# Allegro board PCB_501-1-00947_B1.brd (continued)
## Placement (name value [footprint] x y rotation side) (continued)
R665  10K  [R0402]  25.37 35.81 270 top
R666  2.49K  [R0402]  25.87 37.46 0 top
R667  2.49K  [R0402]  26.51 35.81 90 top
R668  2.49K  [R0402]  28.03 30.73 90 top
R669  11K  [R0402]  39.08 29.08 270 bottom
R674  10K  [R0402]  124.3 47.75 270 top
R678  0E  [R0402]  88.1 42.29 90 top
R679  2.2K  [R0402]  89.25 42.29 270 top
R680  0E  [R0402]  29.56 33.53 180 top
R682  10K  [R0402]  104.74 12.32 180 top
R683  10K  [R0402]  123.16 47.75 90 top
R684  0E  [R0402]  90.9 42.8 180 top
R685  100K  [R0402]  18.13 80.9 270 bottom
R686  100K  [R0402]  22.83 94.36 180 top
R687  100K  [R0402]  19.52 80.9 270 bottom
R688  2.2K  [R0402]  26.89 33.53 180 top
R689  100K  [R0402]  8.6 66.55 0 top
R690  0E  [R0402]  22.83 93.34 0 top
R691  10K  [R0402]  68.04 60.58 0 bottom
R692  100K  [R0402]  118.97 65.91 0 top
R694  523K  [0402]  122.9 71.88 0 top
R695  16.9K  [0402]  121.38 71.88 0 top
R696  120K  [0402]  121.25 73.28 0 top
R697  10K  [R0402]  4.16 9.4 90 top
R698  10K  [R0402]  4.16 12.06 90 top
R699  10K  [R0402]  4.16 14.48 90 top
R700  10K  [R0402]  4.28 17.02 90 top
R701  10K  [R0402]  4.28 19.56 90 top
R702  10K  [R0402]  4.28 22.1 90 top
R703  10K  [R0402]  4.28 24.64 90 top
R704  10K  [R0402]  4.28 27.18 90 top
R705  10K  [R0402]  125.44 9.52 180 top
R706  33E  [R0402]  122.27 13.84 180 top
R707  10K  [R0402]  102.33 17.02 0 bottom
R708  10K  [R0402]  102.33 15.88 0 bottom
R709  10K  [R0402]  102.33 14.73 0 bottom
R710  10K  [R0402]  102.33 13.59 0 bottom
R711  10K  [R0402]  102.33 19.43 0 bottom
R715  100K  [R0402]  82.9 109.22 180 top
R716  10K  [0402]  87.72 115.06 90 top
R717  10K  [0402]  87.72 113.41 90 top
R718  10mE  [0603]  27.53 80.64 0 top
R721  10mE  [0603]  19.02 75.06 0 top
R722  10mE  [0603]  12.41 75.56 270 top
R723  0E  [R0402]  18.38 62.74 270 top
R724  0E  [R0402]  19.52 62.74 270 top
R725  0E  [R0402]  18.25 62.36 270 bottom
R726  0E  [R0402]  19.4 62.36 270 bottom
R727  10K  [R0402]  22.57 66.17 0 top
R728  10mE  [0603]  16.22 96.52 180 top
R729  10mE  [0603]  26.51 84.84 0 top
R730  10mE  [0603]  5.05 84.96 180 top
R731  10K  [R0402]  15.08 66.29 90 bottom
R732  10K  [R0402]  21.05 63.25 0 bottom
R733  0E  [R0402]  21.68 42.42 90 bottom
R734  100K  [R0402]  24.73 42.16 90 bottom
R735  100K  [R0402]  19.52 80.9 90 top
R736  0E  [R0402]  89.76 96.52 180 top
R737  0E  [R0402]  98.01 105.66 270 top
R738  1K  [R0402]  6.57 88.77 0 top
R739  470E  [R0402]  45.56 95.63 135 top
R740  470E  [R0402]  44.42 94.36 135 top
R741  4.7K  [R0402]  41.59 37.16 0 bottom
R742  100K  [R0402]  103.22 61.72 0 bottom
R749  10K  [R0402]  11.52 91.82 270 top
R750  10K  [R0402]  25.24 93.85 90 top
R751  100K  [R0402]  16.35 81.28 180 bottom
R752  0E  [R0402]  12.54 91.82 90 top
R753  100K  [R0402]  69.69 87.25 45 bottom
R754  0E  [R0402]  120.13 26.14 90 top
R755  0E  [R0402]  117.82 26.04 90 top
R756  0E  [R0402]  120.62 25.65 0 top
R757  0E  [R0402]  118.31 25.55 0 top
R758  470E  [R0402]  10.89 53.47 180 top
R762  0E  [R0402]  21.4 95.96 90 top
R763  100K  [R0402]  15.05 78.82 270 bottom
R764  100K  [R0402]  10.35 80.21 270 bottom
SW1  OS102011MS2QN1  [SW3_2_8P6X4P3_TH_ST]  43.53 126.11 0 top
SW2  219-8MST  [SW16_2P54_21P79X6P7_A1]  11.02 18.8 270 top
SW3  219-2MST  [SW4_2P54_6P95X6P55]  11.02 34.42 0 top
SW4  TL6700AF160QG  [SW4_4_6P9X6P2]  4.54 73.28 270 top
SW5  TL6700AF160QG  [SW4_4_6P9X6P2]  102.2 54.36 0 top
SW6  TL6700AF160QG  [SW4_4_6P9X6P2]  102.46 65.79 0 top
SW7  TL6700AF160QG  [SW4_4_6P9X6P2]  121.63 54.36 0 top
SW8  TL6700AF160QG  [SW4_4_6P9X6P2]  88.87 73.03 90 top
SW9  SDA01H0SB  [SW2_8P25_7P49X4P52]  35.53 87.88 0 top
TP1  SMD  [TP30]  20.29 99.06 90 top
TP6  SMD  [TP30]  75.23 82.2 270 top
TP7  SMD  [TP30]  76.34 83.67 225 top
TP8  SMD  [TP30]  78.16 83.41 225 top
TP9  SMD  [TP30]  79.73 82.08 225 top
TP10  SMD  [TP30]  54.45 92.58 180 bottom
TP11  SMD  [TP30]  57.82 91.08 135 bottom
TP14  SMD  [TP30]  66.38 100.43 90 bottom
TP15  SMD  [TP15]  65.93 97.05 0 top
TP16  SMD  [TP15]  71.83 102.1 0 top
TP17  SMD  [TP15]  51.35 101.44 0 top
TP18  SMD  [TP15]  54.34 98.45 0 top
TP19  SMD  [TP30]  67.82 100.46 90 bottom
TP20  SMD  [TP30]  52.42 99.06 270 top
TP21  SMD  [TP15]  69.12 110.34 90 bottom
TP22  SMD  [TP15]  51.68 111.43 180 bottom
TP23  SMD  [TP15]  70.28 111.41 90 bottom
TP24  SMD  [TP15]  52.7 112.32 90 bottom
TP29  SMD  [TP30]  103.85 38.73 270 bottom
TP30  SMD  [TP40_SMD]  24.73 45.72 0 top
TP31  SMD  [TP40_SMD]  5.43 30.23 0 top
TP32  SMD  [TP40_SMD]  6.82 99.95 0 top
TP33  SMD  [TP40_SMD]  63.85 35.94 0 top
TP34  SMD  [TP40_SMD]  68.55 23.62 0 top
TP35  SMD  [TP40_SMD]  124.68 61.34 0 top
TP36  SMD  [TP40_SMD]  78.45 114.17 0 top
TP37  SMD  [TP40_SMD]  76.67 111.51 0 top
TP40  SMD  [TP15]  67.96 101.24 0 top
TP41  SMD  [TP15]  64.29 99.03 0 top
TP42  SMD  [TP15]  68.33 102.18 0 top
TP43  SMD  [TP15]  64 97.91 0 top
TP44  SMD  [TP15]  57.56 97.13 0 top
TP45  SMD  [TP15]  57.28 98.09 0 top
TP46  SMD  [TP15]  53.86 100.86 0 top
TP47  SMD  [TP15]  53.92 101.47 0 top
TP48  SMD  [TP30]  54.53 75.54 90 bottom
TP50  SMD  [TP40_SMD]  113.5 25.53 270 top
TP51  SMD  [TP40_SMD]  115.92 26.04 270 top
TP52  SMD  [TP40_SMD]  123.16 26.04 270 top
TP53  SMD  [TP40_SMD]  122.01 24.26 270 top
TP54  SMD  [TP40_SMD]  125.95 17.4 270 top
TP55  SMD  [TP40_SMD]  125.95 19.18 270 top
TP56  SMD  [TP40_SMD]  103.85 4.06 270 top
TP57  SMD  [TP40_SMD]  105.38 4.06 270 top
TP62  SMD  [TP40_SMD]  49.12 34.29 0 top
TP68  SMD  [TP30]  61.96 108.31 0 top
TP69  SMD  [TP30]  67.95 97.08 0 top
TP70  SMD  [TP30]  76.49 107.96 0 top
TP71  SMD  [TP30]  70.52 118.42 0 top
TP72  SMD  [TP30]  60.03 121.04 0 top
TP73  SMD  [TP30]  46.34 108.31 0 top
TP74  SMD  [TP30]  49.13 118.12 0 top
TP75  SMD  [TP30]  47.78 100.56 0 top
TP76  SMD  [TP30]  82.39 107.7 270 top
TP77  SMD  [TP40_SMD]  11.44 71.16 0 top
TP78  SMD  [TP40_SMD]  25.11 70.1 0 top
TP79  SMD  [TP40_SMD]  31.34 80.52 0 top
TP80  SMD  [TP40_SMD]  7.59 98.04 0 top
TP81  SMD  [TP40_SMD]  28.67 85.72 0 top
TP82  SMD  [TP40_SMD]  2 86.36 0 top
TP83  SMD  [TP40_SMD]  106.41 47.6 270 top
TP84  SMD  [TP40_SMD]  124.93 78.74 0 top
TP85  SMD  [TP40_SMD]  23.21 49.91 0 top
TP86  SMD  [TP40_SMD]  57.04 38.83 0 top
U5  TPS65218D0RSL  [VQFN48_0P4_6X6_EP_A1]  16.48 86.87 180 top
U7  MCIMX7D5EVM10SD  [BGA541X]  60.99 86.3 135 top
U8  MT41K256M16TW-107:P  [BGA96_0P8_8P15X14P15]  70.11 109.22 180 top
U9  MT41K256M16TW-107:P  [BGA96_0P8_8P15X14P15]  52.95 109.22 180 top
U10  MTFC8GAKAJCN-4M  [BGA153_0P5_11P5X13_C_A1]  71.61 59.9 315 top
U11  MT25QL512ABB1EW9  [DFN8_1P27_8X6_EP_A_A1]  44.23 99.59 90 bottom
U13  DP83867CRRGZ  [QFN48_0P5_7X7_EP_O_A1]  35.53 34.54 90 top
U17  SN74LVC2G126DCU  [DCU8P5R]  112.6 110.34 0 bottom
U18  FT2232D  [QFP48P5J]  104.73 112.88 270 bottom
U19  SN74LVC2G126DCU  [DCU8P5R]  102.85 104.55 90 bottom
U23  TSC2046IPW  [TSSOP16FA]  17.65 48.92 90 bottom
U24  WM8960CGEFL  [QFN32_1P5H]  96.54 39.04 180 top
U25  MCP2562-E/MF  [DFN8_0P65_3X3_EP_A]  74.64 23.5 180 top
U30  LM3526MX-L/NOPB  [SOIC8_1P27_4X5]  57.75 17.27 270 bottom
U31  OPT3001DNP  [SON6_0P65_2X2_EP_A_A1]  121 47.24 180 top
U33  SN74LVC1G07DBV  [SOT23-5L_0P95_3P05X1P75]  11.14 58.55 90 top
U37  TPS3808G25  [SOT23-6L_0P95_3P05X1P75]  90.77 93.09 270 top
U41  24AA512  [SO8_1P27_4X5]  91.28 60.96 180 top
U42  PI6CG182Q2ZDQ  [QFN24_0P5_4X4_EP_R_A1]  79.46 97.5 225 top
U45  TXS0102DCU  [SSOP8CR]  29.02 56.83 0 top
U46  TPS62067DSG  [SON8_0P5_2X2_EP]  122.01 65.66 90 top
U47  TLV75528PDQN  [X2SON4_0P65_1X1_EP_A_A1]  28.16 48.13 0 top
U49  TLV75525PDQN  [X2SON4_0P65_1X1_EP_A_A1]  63.09 37.97 0 top
U50  INA3221AIRGV  [QFN16_0P65_4X4_EP_I_A1]  18.89 66.55 0 top
U51  TPS51200DRC  [SON10_0P5_3P1X3P1]  81.88 112.52 180 top
U52  INA3221AIRGV  [QFN16_0P65_4X4_EP_I_A1]  18.89 66.55 180 bottom
U53  PUSB3F96  [DFN2510A-10L_0P5_2P5X1]  25.75 23.5 0 top
U54  PUSB3F96  [DFN2510A-10L_0P5_2P5X1]  31.59 23.5 0 top
U55  BD2204GUL  [VCSP50L1-6_0P5_1P5X1_A1]  103.34 63.5 270 bottom
X1  32.768KHz  [XTAL2_2P5_3P2X1P5]  81.12 86.36 225 top
X2  24MHz  [XTAL4_1P85_3P2X2P5]  76.93 77.72 45 top
X3  25MHz  [XTAL4_1P7_3P2X2P5]  44.67 32 270 top
X4  25MHz  [XTAL2_3P8_5X3P2]  85.18 102.23 135 top
X5  6MHz  [XTAL4_2P54_7X5_A_A1]  92.68 113.41 90 bottom
Y4  24MHz  [OSC4_1P9_3P2X2P5_C_A1]  4.41 47.5 270 bottom
Y5  32.768KHz  [OSC4_3P2X2P5_SMD]  125.19 12.7 90 top

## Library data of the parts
BH1 = BATT_HOLDER_2P
C1 C199 C202-C204 C274 C275 C299 C438 = CAP_POL
C2 C3 C40-C42 C44-C53 C63-C131 C140-C190 C194-C197 C200 C201 C207 C208 C216-C224 C226-C228 C239-C245 C249-C252 C260-C273 C276 C279-C298 C300-C311 C318 C354 C357 C361 C362 C366-C370 C382 C391-C395 C401-C410 C420-C423 C439 C444-C448 C456 C460 C461 C500 C501 C503-C513 C518-C520 C523-C525 C527-C531 C533-C540 C542-C544 C546 C550-C553 C556-C561 C566-C579 = CAP_NP
D1 D2 D6-D11 D14 D33 D35 = DIODE_LED
D4 D16 D20-D22 D26 D34 = DIODE_SCH
D5 = DIODE_LED_A
D17 = DIODE_ZEN
D23 D24 D27-D30 = DIODE_TVS_BIDIR_C_A1
DA1 = DIODE_NETX2_LED-GR_4P
F1 = FUSE
FB2-FB4 FB10-FB14 FB16-FB22 FB31 FB32 FB35-FB42 = FER_BEAD
FD1-FD6 = MECH_FID_G
FD7-FD14 = MECH_FID_L
FL1 FL2 = FIL_COM-MODE_4P_C_POL
FL3 = FIL_COM-MODE_4P_C_POL: signal model: FIL_COM-MODE_4P_C_POL_CM_CHK4_0
H1 H2 = HDR_2X5_10P
H3 = HDR_1X4_4P
H4 = HDR_1X3_3P
H5 = HDR_1X6_6P
J1 = CONN_PWRJACK_4P_A_A1
J2 = CONN_B2C_1X2_2P
J3 J4 J10 = CONN_COAX_3P
J7 = CONN_SIMCARD_8P
J8 = CONN_MINI-PCIEXPRESS-52_54P_A
J11 = CONN_USB-5X1_11P
J14 = CONN_FPC-50_52P
J15 = CONN_AUDJACK_4P
J19 = CONN_DB9X1_11P
J20 = CONN_B2B_2X15_34P_A
J25 = CONN_USB-5X1_7P
J26 = CONN_USBA-4X1_8P
J27 = CONN_RJ45-14X1_16P_A
J28 = CONN_SD-CARD-11_14P_A1
L3-L6 = IND_CORE_A
L7 = IND_CORE_B
L8 = IND_POL
M1 = MODRF_WL1831_100P
MECH1-MECH4 = MECH_STANDOFF_A1
MH1-MH4 = MECH_MH_PL
MK1 = MICROPHONE
P4-P8 P10-P14 P17-P27 = PROT_ZENX2_NET_2P_A
Q2 Q32 Q34 = TRANS_PMOSX1_8P
Q5 Q7 Q25 Q37 Q39 = TRANS_NMOS-ENX1_3P
Q6 Q24 = TRANS_PMOS-ENX1_3P_E
Q8 Q40 Q41 = TRANS_NPN
Q17 = TRANS_PNP
Q35 = TRANS_PNPX2_6P_A1
Q38 = TRANS_PMOS-ENX1_3P_C
R1 R4 R6 R8 R12 R30-R38 R45-R47 R49 R61-R71 R75 R76 R80-R86 R90-R94 R99 R102-R105 R107-R110 R116-R118 R125-R127 R129-R131 R145-R147 R155 R157-R172 R174 R176-R182 R203 R204 R206 R209-R213 R224 R231-R238 R242 R245-R247 R249-R255 R257 R269 R284 R285 R293-R297 R301-R303 R307-R310 R325 R347-R350 R356-R358 R366 R367 R380 R381 R387 R483 R485-R487 R491 R504 R506 R508 R509 R515 R516 R520 R521 R537-R539 R558 R559 R565-R571 R590-R593 R595-R598 R604-R608 R613-R618 R622 R623 R630 R632-R641 R644 R645 R656 R658 R660 R663-R669 R674 R678-R680 R682-R692 R694-R711 R715-R718 R721-R742 R749-R758 R762-R764 = RES
R39-R44 R100 R101 R106 = RES: signal model: sd1
R95-R97 R124 R278-R283 R300 R306 R436-R447 = RES: signal model: sd3
R286-R291 = RES: signal model: sd2
R448 R449 = RES: signal model: nand
R525-R528 R530 R532 = RES: signal model: RGMII1_TX
SW1 = SWITCH_SPDT_5P
SW2 = SWITCH_DIPX8_16P_B
SW3 = SWITCH_DIPX2_4P_B
SW4-SW8 = SWITCH_PUSH_4P
SW9 = SWITCH_DIPX1_2P_B
TP1 TP6-TP11 TP14-TP24 TP29-TP37 TP40-TP48 TP50-TP57 TP62 TP68-TP86 = TEST_POINT_SMD
U5 = IC_TPS65218D0_QFN-48P_EP_A1
U7 = IC_IMX7D_BGA-541P_CUST_A1
U8 U9 = IC_DDR3-SDRAM_BGA-96P_CUST_A1
U10 = IC_NAND_FLASHx8_BGA-153P_J_A1
U11 = IC_NORFLASH-SPI_8P_EP_G_A1
U13 = IC_DP83867_VQFN-48P_EP_A_A1
U17 U19 = IC_GATE_BUFX2_8P_B_A1
U18 = IC_FT2232D_LQFP-48P_A1
U23 = IC_TSC2046_TSSOP-16P_A1
U24 = IC_AUDIO-CODEC_32P_EP_A_A1
U25 = IC_CAN-XCVR_8P_EP_A2
U30 = IC_LM3526-L_SOIC-8P
U31 = IC_LIGHT-SENSOR_6P_EP_B_A1
U33 = IC_GATE_BUFX1_5P
U37 = IC_VOLT-MONITOR_6P
U41 = IC_EEPROM-I2C_8P_C
U42 = IC_CLOCK-GENERATOR_24P_EP_C_A1
U45 = IC_TXS0102_8P_A
U46 = IC_TPS62067_WSON-8P_EP
U47 U49 = IC_LDO-FIXED_4P_EP_A_A2
U50 U52 = IC_INA3221_VQFN-16P_EP_A1
U51 = IC_TPS51200_SON-10P_EP
U53 U54 = IC_PUSB3F96_DFN-10P
U55 = IC_BD2204_CSP-6P_A1
X1 X4 = CRYSTAL
X2 X3 X5 = CRYSTAL_4P
Y4 = OSC_4P_R_A1
Y5 = OSC_4P_A

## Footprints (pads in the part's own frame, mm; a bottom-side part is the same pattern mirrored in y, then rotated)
0402
  rect 0.533x0.533 smd: 1(-0.4,0) 2(0.4,0)
0603
  rect 0.965x1.016 smd: 1(-0.8,0) 2(0.8,0)
0805_B_A1
  rect 0.711x1.321 smd: 1(-0.95,0) 2(0.95,0)
BGA96_0P8_8P15X14P15
  round 0.356 smd: A1(-3.2,6) A2(-2.4,6) A3(-1.6,6) A7(1.6,6) A8(2.4,6) A9(3.2,6) B1(-3.2,5.2) B2(-2.4,5.2) B3(-1.6,5.2) B7(1.6,5.2) B8(2.4,5.2) B9(3.2,5.2) C1(-3.2,4.4) C2(-2.4,4.4) C3(-1.6,4.4) C7(1.6,4.4) C8(2.4,4.4) C9(3.2,4.4) D1(-3.2,3.6) D2(-2.4,3.6) D3(-1.6,3.6) D7(1.6,3.6) D8(2.4,3.6) D9(3.2,3.6) E1(-3.2,2.8) E2(-2.4,2.8) E3(-1.6,2.8) E7(1.6,2.8) E8(2.4,2.8) E9(3.2,2.8) F1(-3.2,2) F2(-2.4,2) F3(-1.6,2) F7(1.6,2) F8(2.4,2) F9(3.2,2) G1(-3.2,1.2) G2(-2.4,1.2) G3(-1.6,1.2) G7(1.6,1.2) G8(2.4,1.2) G9(3.2,1.2) H1(-3.2,0.4) H2(-2.4,0.4) H3(-1.6,0.4) H7(1.6,0.4) H8(2.4,0.4) H9(3.2,0.4) J1(-3.2,-0.4) J2(-2.4,-0.4) J3(-1.6,-0.4) J7(1.6,-0.4) J8(2.4,-0.4) J9(3.2,-0.4) K1(-3.2,-1.2) K2(-2.4,-1.2) K3(-1.6,-1.2) K7(1.6,-1.2) K8(2.4,-1.2) K9(3.2,-1.2) L1(-3.2,-2) L2(-2.4,-2) L3(-1.6,-2) L7(1.6,-2) L8(2.4,-2) L9(3.2,-2) M1(-3.2,-2.8) M2(-2.4,-2.8) M3(-1.6,-2.8) M7(1.6,-2.8) M8(2.4,-2.8) M9(3.2,-2.8) N1(-3.2,-3.6) N2(-2.4,-3.6) N3(-1.6,-3.6) N7(1.6,-3.6) N8(2.4,-3.6) N9(3.2,-3.6) P1(-3.2,-4.4) P2(-2.4,-4.4) P3(-1.6,-4.4) P7(1.6,-4.4) P8(2.4,-4.4) P9(3.2,-4.4) R1(-3.2,-5.2) R2(-2.4,-5.2) R3(-1.6,-5.2) R7(1.6,-5.2) R8(2.4,-5.2) R9(3.2,-5.2) T1(-3.2,-6) T2(-2.4,-6) T3(-1.6,-6) T7(1.6,-6) T8(2.4,-6) T9(3.2,-6)
BGA153_0P5_11P5X13_C_A1
  round 0.254 smd: A1(-3.25,3.25) A2(-2.75,3.25) A3(-2.25,3.25) A4(-1.75,3.25) A5(-1.25,3.25) A6(-0.75,3.25) A7(-0.25,3.25) A8(0.25,3.25) A9(0.75,3.25) A10(1.25,3.25) A11(1.75,3.25) A12(2.25,3.25) A13(2.75,3.25) A14(3.25,3.25) B1(-3.25,2.75) B2(-2.75,2.75) B3(-2.25,2.75) B4(-1.75,2.75) B5(-1.25,2.75) B6(-0.75,2.75) B7(-0.25,2.75) B8(0.25,2.75) B9(0.75,2.75) B10(1.25,2.75) B11(1.75,2.75) B12(2.25,2.75) B13(2.75,2.75) B14(3.25,2.75) C1(-3.25,2.25) C2(-2.75,2.25) C3(-2.25,2.25) C4(-1.75,2.25) C5(-1.25,2.25) C6(-0.75,2.25) C7(-0.25,2.25) C8(0.25,2.25) C9(0.75,2.25) C10(1.25,2.25) C11(1.75,2.25) C12(2.25,2.25) C13(2.75,2.25) C14(3.25,2.25) D1(-3.25,1.75) D2(-2.75,1.75) D3(-2.25,1.75) D4(-1.75,1.75) D12(2.25,1.75) D13(2.75,1.75) D14(3.25,1.75) E1(-3.25,1.25) E2(-2.75,1.25) E3(-2.25,1.25) E5(-1.25,1.25) E6(-0.75,1.25) E7(-0.25,1.25) E8(0.25,1.25) E9(0.75,1.25) E10(1.25,1.25) E12(2.25,1.25) E13(2.75,1.25) E14(3.25,1.25) F1(-3.25,0.75) F2(-2.75,0.75) F3(-2.25,0.75) F5(-1.25,0.75) F10(1.25,0.75) F12(2.25,0.75) F13(2.75,0.75) F14(3.25,0.75) G1(-3.25,0.25) G2(-2.75,0.25) G3(-2.25,0.25) G5(-1.25,0.25) G10(1.25,0.25) G12(2.25,0.25) G13(2.75,0.25) G14(3.25,0.25) H1(-3.25,-0.25) H2(-2.75,-0.25) H3(-2.25,-0.25) H5(-1.25,-0.25) H10(1.25,-0.25) H12(2.25,-0.25) H13(2.75,-0.25) H14(3.25,-0.25) J1(-3.25,-0.75) J2(-2.75,-0.75) J3(-2.25,-0.75) J5(-1.25,-0.75) J10(1.25,-0.75) J12(2.25,-0.75) J13(2.75,-0.75) J14(3.25,-0.75) K1(-3.25,-1.25) K2(-2.75,-1.25) K3(-2.25,-1.25) K5(-1.25,-1.25) K6(-0.75,-1.25) K7(-0.25,-1.25) K8(0.25,-1.25) K9(0.75,-1.25) K10(1.25,-1.25) K12(2.25,-1.25) K13(2.75,-1.25) K14(3.25,-1.25) L1(-3.25,-1.75) L2(-2.75,-1.75) L3(-2.25,-1.75) L12(2.25,-1.75) L13(2.75,-1.75) L14(3.25,-1.75) M1(-3.25,-2.25) M2(-2.75,-2.25) M3(-2.25,-2.25) M4(-1.75,-2.25) M5(-1.25,-2.25) M6(-0.75,-2.25) M7(-0.25,-2.25) M8(0.25,-2.25) M9(0.75,-2.25) M10(1.25,-2.25) M11(1.75,-2.25) M12(2.25,-2.25) M13(2.75,-2.25) M14(3.25,-2.25) N1(-3.25,-2.75) N2(-2.75,-2.75) N3(-2.25,-2.75) N4(-1.75,-2.75) N5(-1.25,-2.75) N6(-0.75,-2.75) N7(-0.25,-2.75) N8(0.25,-2.75) N9(0.75,-2.75) N10(1.25,-2.75) N11(1.75,-2.75) N12(2.25,-2.75) N13(2.75,-2.75) N14(3.25,-2.75) P1(-3.25,-3.25) P2(-2.75,-3.25) P3(-2.25,-3.25) P4(-1.75,-3.25) P5(-1.25,-3.25) P6(-0.75,-3.25) P7(-0.25,-3.25) P8(0.25,-3.25) P9(0.75,-3.25) P10(1.25,-3.25) P11(1.75,-3.25) P12(2.25,-3.25) P13(2.75,-3.25) P14(3.25,-3.25)
BGA541X
  round 0.381 smd: A1(-9,9) A2(-8.25,9) A3(-7.5,9) A4(-6.75,9) A5(-6,9) A6(-5.25,9) A7(-4.5,9) A8(-3.75,9) A9(-3,9) A10(-2.25,9) A11(-1.5,9) A12(-0.75,9) A13(0,9) A14(0.75,9) A15(1.5,9) A16(2.25,9) A17(3,9) A18(3.75,9) A19(4.5,9) A20(5.25,9) A21(6,9) A22(6.75,9) A23(7.5,9) A24(8.25,9) A25(9,9) AA1(-9,-6) AA2(-8.25,-6) AA3(-7.5,-6) AA4(-6.75,-6) AA5(-6,-6) AA6(-5.25,-6) AA7(-4.5,-6) AA8(-3.75,-6) AA9(-3,-6) AA10(-2.25,-6) AA11(-1.5,-6) AA12(-0.75,-6) AA13(0,-6) AA14(0.75,-6) AA15(1.5,-6) AA16(2.25,-6) AA17(3,-6) AA18(3.75,-6) AA19(4.5,-6) AA20(5.25,-6) AA21(6,-6) AA22(6.75,-6) AA23(7.5,-6) AA24(8.25,-6) AA25(9,-6) AB1(-9,-6.75) AB2(-8.25,-6.75) AB3(-7.5,-6.75) AB4(-6.75,-6.75) AB5(-6,-6.75) AB6(-5.25,-6.75) AB7(-4.5,-6.75) AB8(-3.75,-6.75) AB9(-3,-6.75) AB10(-2.25,-6.75) AB11(-1.5,-6.75) AB12(-0.75,-6.75) AB13(0,-6.75) AB14(0.75,-6.75) AB15(1.5,-6.75) AB16(2.25,-6.75) AB17(3,-6.75) AB18(3.75,-6.75) AB19(4.5,-6.75) AB20(5.25,-6.75) AB21(6,-6.75) AB22(6.75,-6.75) AB23(7.5,-6.75) AB24(8.25,-6.75) AB25(9,-6.75) AC1(-9,-7.5) AC2(-8.25,-7.5) AC3(-7.5,-7.5) AC4(-6.75,-7.5) AC5(-6,-7.5) AC6(-5.25,-7.5) AC7(-4.5,-7.5) AC8(-3.75,-7.5) AC9(-3,-7.5) AC10(-2.25,-7.5) AC11(-1.5,-7.5) AC12(-0.75,-7.5) AC13(0,-7.5) AC14(0.75,-7.5) AC15(1.5,-7.5) AC16(2.25,-7.5) AC17(3,-7.5) AC18(3.75,-7.5) AC19(4.5,-7.5) AC20(5.25,-7.5) AC21(6,-7.5) AC22(6.75,-7.5) AC23(7.5,-7.5) AC24(8.25,-7.5) AC25(9,-7.5) AD1(-9,-8.25) AD2(-8.25,-8.25) AD3(-7.5,-8.25) AD4(-6.75,-8.25) AD5(-6,-8.25) AD6(-5.25,-8.25) AD7(-4.5,-8.25) AD8(-3.75,-8.25) AD9(-3,-8.25) AD10(-2.25,-8.25) AD11(-1.5,-8.25) AD12(-0.75,-8.25) AD13(0,-8.25) AD14(0.75,-8.25) AD15(1.5,-8.25) AD16(2.25,-8.25) AD17(3,-8.25) AD18(3.75,-8.25) AD19(4.5,-8.25) AD20(5.25,-8.25) AD21(6,-8.25) AD22(6.75,-8.25) AD23(7.5,-8.25) AD24(8.25,-8.25) AD25(9,-8.25) AE1(-9,-9) AE2(-8.25,-9) AE3(-7.5,-9) AE4(-6.75,-9) AE5(-6,-9) AE6(-5.25,-9) AE7(-4.5,-9) AE8(-3.75,-9) AE9(-3,-9) AE10(-2.25,-9) AE11(-1.5,-9) AE12(-0.75,-9) AE13(0,-9) AE14(0.75,-9) AE15(1.5,-9) AE16(2.25,-9) AE17(3,-9) AE18(3.75,-9) AE19(4.5,-9) AE20(5.25,-9) AE21(6,-9) AE22(6.75,-9) AE23(7.5,-9) AE24(8.25,-9) AE25(9,-9) B1(-9,8.25) B2(-8.25,8.25) B3(-7.5,8.25) B4(-6.75,8.25) B5(-6,8.25) B6(-5.25,8.25) B7(-4.5,8.25) B8(-3.75,8.25) B9(-3,8.25) B10(-2.25,8.25) B11(-1.5,8.25) B12(-0.75,8.25) B13(0,8.25) B14(0.75,8.25) B15(1.5,8.25) B16(2.25,8.25) B17(3,8.25) B18(3.75,8.25) B19(4.5,8.25) B20(5.25,8.25) B21(6,8.25) B22(6.75,8.25) B23(7.5,8.25) B24(8.25,8.25) B25(9,8.25) C1(-9,7.5) C2(-8.25,7.5) C3(-7.5,7.5) C4(-6.75,7.5) C5(-6,7.5) C6(-5.25,7.5) C7(-4.5,7.5) C8(-3.75,7.5) C9(-3,7.5) C10(-2.25,7.5) C11(-1.5,7.5) C12(-0.75,7.5) C13(0,7.5) C14(0.75,7.5) C15(1.5,7.5) C16(2.25,7.5) C17(3,7.5) C18(3.75,7.5) C19(4.5,7.5) C20(5.25,7.5) C21(6,7.5) C22(6.75,7.5) C23(7.5,7.5) C24(8.25,7.5) C25(9,7.5) D1(-9,6.75) D2(-8.25,6.75) D3(-7.5,6.75) D4(-6.75,6.75) D5(-6,6.75) D6(-5.25,6.75) D7(-4.5,6.75) D8(-3.75,6.75) D9(-3,6.75) D10(-2.25,6.75) D11(-1.5,6.75) D12(-0.75,6.75) D13(0,6.75) D14(0.75,6.75) D15(1.5,6.75) D16(2.25,6.75) D17(3,6.75) D18(3.75,6.75) D19(4.5,6.75) D20(5.25,6.75) D21(6,6.75) D22(6.75,6.75) D23(7.5,6.75) D24(8.25,6.75) D25(9,6.75) E1(-9,6) E2(-8.25,6) E3(-7.5,6) E4(-6.75,6) E5(-6,6) E6(-5.25,6) E7(-4.5,6) E8(-3.75,6) E9(-3,6) E10(-2.25,6) E11(-1.5,6) E12(-0.75,6) E13(0,6) E14(0.75,6) E15(1.5,6) E16(2.25,6) E17(3,6) E18(3.75,6) E19(4.5,6) E20(5.25,6) E21(6,6) E22(6.75,6) E23(7.5,6) E24(8.25,6) E25(9,6) F1(-9,5.25) F2(-8.25,5.25) F3(-7.5,5.25) F4(-6.75,5.25) F5(-6,5.25) F6(-5.25,5.25) F7(-4.5,5.25) F8(-3.75,5.25) F9(-3,5.25) F10(-2.25,5.25) F11(-1.5,5.25) F12(-0.75,5.25) F13(0,5.25) F14(0.75,5.25) F15(1.5,5.25) F16(2.25,5.25) F17(3,5.25) F18(3.75,5.25) F19(4.5,5.25) F20(5.25,5.25) F21(6,5.25) F22(6.75,5.25) F23(7.5,5.25) F24(8.25,5.25) F25(9,5.25) G1(-9,4.5) G2(-8.25,4.5) G3(-7.5,4.5) G4(-6.75,4.5) G5(-6,4.5) G6(-5.25,4.5) G7(-4.5,4.5) G9(-3,4.5) G11(-1.5,4.5) G13(0,4.5) G15(1.5,4.5) G17(3,4.5) G19(4.5,4.5) G20(5.25,4.5) G21(6,4.5) G22(6.75,4.5) G23(7.5,4.5) G24(8.25,4.5) G25(9,4.5) H1(-9,3.75) H2(-8.25,3.75) H3(-7.5,3.75) H4(-6.75,3.75) H5(-6,3.75) H6(-5.25,3.75) H8(-3.75,3.75) H10(-2.25,3.75) H12(-0.75,3.75) H14(0.75,3.75) H16(2.25,3.75) H18(3.75,3.75) H20(5.25,3.75) H21(6,3.75) H22(6.75,3.75) H23(7.5,3.75) H24(8.25,3.75) H25(9,3.75) J1(-9,3) J2(-8.25,3) J3(-7.5,3) J4(-6.75,3) J5(-6,3) J6(-5.25,3) J7(-4.5,3) J9(-3,3) J11(-1.5,3) J13(0,3) J15(1.5,3) J17(3,3) J19(4.5,3) J20(5.25,3) J21(6,3) J22(6.75,3) J23(7.5,3) J24(8.25,3) J25(9,3) K1(-9,2.25) K2(-8.25,2.25) K3(-7.5,2.25) K4(-6.75,2.25) K5(-6,2.25) K6(-5.25,2.25) K8(-3.75,2.25) K10(-2.25,2.25) K12(-0.75,2.25) K14(0.75,2.25) K16(2.25,2.25) K18(3.75,2.25) K20(5.25,2.25) K21(6,2.25) K22(6.75,2.25) K23(7.5,2.25) K24(8.25,2.25) K25(9,2.25) L1(-9,1.5) L2(-8.25,1.5) L3(-7.5,1.5) L4(-6.75,1.5) L5(-6,1.5) L6(-5.25,1.5) L7(-4.5,1.5) L9(-3,1.5) L11(-1.5,1.5) L13(0,1.5) L15(1.5,1.5) L17(3,1.5) L19(4.5,1.5) L20(5.25,1.5) L21(6,1.5) L22(6.75,1.5) L23(7.5,1.5) L24(8.25,1.5) L25(9,1.5) M1(-9,0.75) M2(-8.25,0.75) M3(-7.5,0.75) M4(-6.75,0.75) M5(-6,0.75) M6(-5.25,0.75) M8(-3.75,0.75) M10(-2.25,0.75) M12(-0.75,0.75) M14(0.75,0.75) M16(2.25,0.75) M18(3.75,0.75) M20(5.25,0.75) M21(6,0.75) M22(6.75,0.75) M23(7.5,0.75) M24(8.25,0.75) M25(9,0.75) N1(-9,0) N2(-8.25,0) N3(-7.5,0) N4(-6.75,0) N5(-6,0) N6(-5.25,0) N7(-4.5,0) N9(-3,0) N11(-1.5,0) N13(0,0) N15(1.5,0) N17(3,0) N19(4.5,0) N20(5.25,0) N21(6,0) N22(6.75,0) N23(7.5,0) N24(8.25,0) N25(9,0) P1(-9,-0.75) P2(-8.25,-0.75) P3(-7.5,-0.75) P4(-6.75,-0.75) P5(-6,-0.75) P6(-5.25,-0.75) P8(-3.75,-0.75) P10(-2.25,-0.75) P12(-0.75,-0.75) P14(0.75,-0.75) P16(2.25,-0.75) P18(3.75,-0.75) P20(5.25,-0.75) P21(6,-0.75) P22(6.75,-0.75) P23(7.5,-0.75) P24(8.25,-0.75) P25(9,-0.75) R1(-9,-1.5) R2(-8.25,-1.5) R3(-7.5,-1.5) R4(-6.75,-1.5) R5(-6,-1.5) R6(-5.25,-1.5) R7(-4.5,-1.5) R9(-3,-1.5) R11(-1.5,-1.5) R13(0,-1.5) R15(1.5,-1.5) R17(3,-1.5) R19(4.5,-1.5) R20(5.25,-1.5) R21(6,-1.5) R22(6.75,-1.5) R23(7.5,-1.5) R24(8.25,-1.5) R25(9,-1.5) T1(-9,-2.25) T2(-8.25,-2.25) T3(-7.5,-2.25) T4(-6.75,-2.25) T5(-6,-2.25) T6(-5.25,-2.25) T8(-3.75,-2.25) T10(-2.25,-2.25) T12(-0.75,-2.25) T14(0.75,-2.25) T16(2.25,-2.25) T18(3.75,-2.25) T20(5.25,-2.25) T21(6,-2.25) T22(6.75,-2.25) T23(7.5,-2.25) T24(8.25,-2.25) T25(9,-2.25) U1(-9,-3) U2(-8.25,-3) U3(-7.5,-3) U4(-6.75,-3) U5(-6,-3) U6(-5.25,-3) U7(-4.5,-3) U9(-3,-3) U11(-1.5,-3) U13(0,-3) U15(1.5,-3) U17(3,-3) U19(4.5,-3) U20(5.25,-3) U21(6,-3) U22(6.75,-3) U23(7.5,-3) U24(8.25,-3) U25(9,-3) V1(-9,-3.75) V2(-8.25,-3.75) V3(-7.5,-3.75) V4(-6.75,-3.75) V5(-6,-3.75) V6(-5.25,-3.75) V8(-3.75,-3.75) V10(-2.25,-3.75) V12(-0.75,-3.75) V14(0.75,-3.75) V16(2.25,-3.75) V18(3.75,-3.75) V20(5.25,-3.75) V21(6,-3.75) V22(6.75,-3.75) V23(7.5,-3.75) V24(8.25,-3.75) V25(9,-3.75) W1(-9,-4.5) W2(-8.25,-4.5) W3(-7.5,-4.5) W4(-6.75,-4.5) W5(-6,-4.5) W6(-5.25,-4.5) W7(-4.5,-4.5) W9(-3,-4.5) W11(-1.5,-4.5) W13(0,-4.5) W15(1.5,-4.5) W17(3,-4.5) W19(4.5,-4.5) W20(5.25,-4.5) W21(6,-4.5) W22(6.75,-4.5) W23(7.5,-4.5) W24(8.25,-4.5) W25(9,-4.5) Y1(-9,-5.25) Y2(-8.25,-5.25) Y3(-7.5,-5.25) Y4(-6.75,-5.25) Y5(-6,-5.25) Y6(-5.25,-5.25) Y7(-4.5,-5.25) Y8(-3.75,-5.25) Y9(-3,-5.25) Y10(-2.25,-5.25) Y11(-1.5,-5.25) Y12(-0.75,-5.25) Y13(0,-5.25) Y14(0.75,-5.25) Y15(1.5,-5.25) Y16(2.25,-5.25) Y17(3,-5.25) Y18(3.75,-5.25) Y19(4.5,-5.25) Y20(5.25,-5.25) Y21(6,-5.25) Y22(6.75,-5.25) Y23(7.5,-5.25) Y24(8.25,-5.25) Y25(9,-5.25)
C0402
  rect 0.508x0.559 smd: 1(-0.483,0) 2(0.483,0)
C0603
  rect 0.762x0.889 smd: 1(-0.711,0) 2(0.711,0)
CM_CHK4_0P8_2X1P2
  rect 0.813x0.508 smd: 1(-1.05,-0.4) 2(1.05,-0.4) 3(1.05,0.4) 4(-1.05,0.4)
CON_A-JACK3P5MM_4F_SM_RA
  round 0.508 hole 1.702 unplated: (-3.048,-0.127) (3.952,-0.127)
  rect 2.21x2.819 smd: 1(-3.6,-3.7) 3(-1.6,3.7)
  rect 2.819x2.819 smd: 2(5.8,-3.7) 4(9.7,0.75)
CON_B2B_2X5M_1P27_SM_ST
  rect 0.762x2.413 smd: 1(-2.54,-1.95) 2(-2.54,1.95) 3(-1.27,-1.95) 4(-1.27,1.95) 5(0,-1.95) 6(0,1.95) 7(1.27,-1.95) 8(1.27,1.95) 9(2.54,-1.95) 10(2.54,1.95)
CON_B2C_1X2M_2_TH_ST_A
  rect 1.143x1.143 hole 0.711: 1(0,0)
  round 1.143 hole 0.711: 2(2,0)
CON_BATTERY_2F_30P97_SM
  rect 3.302x3.302 smd: 1(-15.485,0) 2(15.485,0)
CON_BERG_1X4M_2P54_SM_ST_A_A1
  rect 1.27x2.972 smd: 1(-3.81,1.8) 2(-1.27,-1.8) 3(1.27,1.8) 4(3.81,-1.8)
CON_BERG_2X5M_2P54_TH_RA
  rect 1.854x1.854 hole 1.092: 1(0,0)
  round 1.854 hole 1.092: 2(0,-2.54) 3(2.54,0) 4(2.54,-2.54) 5(5.08,0) 6(5.08,-2.54) 7(7.62,0) 8(7.62,-2.54) 9(10.16,0) 10(10.16,-2.54)
CON_BERG_3M_2P54_TH_54101
  rect 1.803x1.803 hole 1.041: 1(0,0)
  round 1.803 hole 1.041: 2(2.54,0) 3(5.08,0)
CON_BERG_6M_2P54_TH
  rect 1.651x1.651 hole 1.016: 1(0,0)
  round 1.651 hole 1.016: 2(2.54,0) 3(5.08,0) 4(7.62,0) 5(10.16,0) 6(12.7,0)
CON_COAXIAL_3F_1P475_SM_ST
  rect 1.016x1.067 smd: 1(0,-1.525)
  rect 1.067x2.21 smd: 2(-1.475,0) 3(1.475,0)
CON_DB_9M_2P74_5747840-4
  rect 1.803x1.803 hole 1.041: 1(0,0)
  round 1.803 hole 1.041: 2(2.74,0) 3(5.48,0) 4(8.22,0) 5(10.96,0) 6(1.37,-2.84) 7(4.11,-2.84) 8(6.85,-2.84) 9(9.59,-2.84)
  round 3.937 hole 3.175: SH1(-7.02,-1.42) SH2(17.97,-1.42)
CON_FPC_50F_0P5_SM_RA
  rect 0.305x1.295 smd: 1(-12.25,3.8) 2(-11.75,3.8) 3(-11.25,3.8) 4(-10.75,3.8) 5(-10.25,3.8) 6(-9.75,3.8) 7(-9.25,3.8) 8(-8.75,3.8) 9(-8.25,3.8) 10(-7.75,3.8) 11(-7.25,3.8) 12(-6.75,3.8) 13(-6.25,3.8) 14(-5.75,3.8) 15(-5.25,3.8) 16(-4.75,3.8) 17(-4.25,3.8) 18(-3.75,3.8) 19(-3.25,3.8) 20(-2.75,3.8) 21(-2.25,3.8) 22(-1.75,3.8) 23(-1.25,3.8) 24(-0.75,3.8) 25(-0.25,3.8) 26(0.25,3.8) 27(0.75,3.8) 28(1.25,3.8) 29(1.75,3.8) 30(2.25,3.8) 31(2.75,3.8) 32(3.25,3.8) 33(3.75,3.8) 34(4.25,3.8) 35(4.75,3.8) 36(5.25,3.8) 37(5.75,3.8) 38(6.25,3.8) 39(6.75,3.8) 40(7.25,3.8) 41(7.75,3.8) 42(8.25,3.8) 43(8.75,3.8) 44(9.25,3.8) 45(9.75,3.8) 46(10.25,3.8) 47(10.75,3.8) 48(11.25,3.8) 49(11.75,3.8) 50(12.25,3.8)
  rect 1.803x2.21 smd: M1(-14.4,-1.85) M2(14.4,-1.85)
CON_PCI_2X26F_0P8_SM_RA_CUST_A1
  round 0.762 hole 1.6 unplated: (-12.5,0)
  round 0.762 hole 2.667 unplated: (-12.1,23.9) (-12.1,48.05) (12.1,23.9) (12.1,48.05)
  round 0.381 hole 1.118 unplated: (12.5,0)
  rect 0.61x2.007 smd: 1(-11.8,-4.1) 2(-11.4,4.1) 3(-11,-4.1) 4(-10.6,4.1) 5(-10.2,-4.1) 6(-9.8,4.1) 7(-9.4,-4.1) 8(-9,4.1) 9(-8.6,-4.1) 10(-8.2,4.1) 11(-7.8,-4.1) 12(-7.4,4.1) 13(-7,-4.1) 14(-6.6,4.1) 15(-6.2,-4.1) 16(-5.8,4.1) 17(-2.2,-4.1) 18(-1.8,4.1) 19(-1.4,-4.1) 20(-1,4.1) 21(-0.6,-4.1) 22(-0.2,4.1) 23(0.2,-4.1) 24(0.6,4.1) 25(1,-4.1) 26(1.4,4.1) 27(1.8,-4.1) 28(2.2,4.1) 29(2.6,-4.1) 30(3,4.1) 31(3.4,-4.1) 32(3.8,4.1) 33(4.2,-4.1) 34(4.6,4.1) 35(5,-4.1) 36(5.4,4.1) 37(5.8,-4.1) 38(6.2,4.1) 39(6.6,-4.1) 40(7,4.1) 41(7.4,-4.1) 42(7.8,4.1) 43(8.2,-4.1) 44(8.6,4.1) 45(9,-4.1) 46(9.4,4.1) 47(9.8,-4.1) 48(10.2,4.1) 49(10.6,-4.1) 50(11,4.1) 51(11.4,-4.1) 52(11.8,4.1)
  rect 2.311x3.2 smd: S1(-14.65,-3.5) S2(14.65,-3.5)
CON_PWR-JACK_2M_6_TH_RA_A_A1
  round 0.991 hole 1.6 unplated: (0,9)
  rect 5.41x2.007 hole 2.997x0.991: 1(0,0)
  rect 4.14x2.007 hole 2.311x0.991: 2(0,6)
  rect 2.007x4.496 hole 0.991x2.489: S1(-4.5,7) S2(4.5,7)
CON_RJ45_14F_2P54_TH_RA
  round 0.508 hole 3.251 unplated: (-11.43,8.89) (0,8.89)
  rect 1.676x1.676 hole 0.914: 1(0,0)
  round 1.676 hole 0.914: 2(-1.27,2.54) 3(-2.54,0) 4(-3.81,2.54) 5(-5.08,0) 6(-6.35,2.54) 7(-7.62,0) 8(-8.89,2.54) 9(-10.16,0) 10(-11.43,2.54)
  round 1.803 hole 1.041: 11(0.915,12.97) 12(-1.625,12.97) 13(-9.805,12.97) 14(-12.345,12.97)
  round 2.362 hole 1.6: SH1(-13.46,5.84) SH2(2.03,5.84)
CON_SDCARD_11F_2P5_SM_RA_A_A1
  round 0.33 hole 1.092 unplated: (-11.5,6.256)
  round 0.762 hole 1.6 unplated: (9.5,6.256)
  rect 1.016x1.499 smd: 1(6.875,9.055) 2(4.375,9.055) 3(1.875,9.055) 4(-0.625,9.055) 5(-3.125,9.055) 6(-5.625,9.055) 7(-8.05,9.055) 8(-9.75,9.055) 9(9.375,9.055)
  rect 0.711x1.499 smd: 10(-11.05,9.055) 11(-12.25,9.055)
  rect 1.499x2.794 smd: S1(-13.651,7.253) S2(11.451,7.253) S3(-13.651,-7.253) S4(13.651,-7.253)
CON_SIM-CARD_8P_2P54_SM_RA
  round 0.381 hole 1.422 unplated: (-6.35,10.16) (6.35,10.16)
  rect 1.295x1.499 smd: C1(-3.81,12.35) C2(-1.27,12.35) C3(1.27,12.35) C4(3.81,12.35) C5(-3.81,-12.35) C6(-1.27,-12.35) C7(1.27,-12.35) C8(3.81,-12.35)
CON_USB-A_1X1F_2_TH_RA_D_A1
  rect 1.549x1.549 hole 0.914: 1(0,0)
  round 1.549 hole 0.914: 2(0,2) 3(0,4) 4(0,6)
  round 2.261 hole 1.346: S1(-2.72,-0.73) S2(2.72,-0.73) S3(-2.72,6.27) S4(2.72,6.27)
CON_USB_1X1-5F_0P65_SM_RA_D_A1
  rect 0.406x1.346 smd: 1(-1.3,0) 2(-0.65,0) 3(0,0) 4(0.65,0) 5(1.3,0)
  rect 1.6x1.397 smd: S1(-3.2,-0.225) S2(3.2,-0.225)
  oval 0.914x1.6 hole 0.508x1.194: S3(3.3,-2.675) S4(-3.3,-2.675)
  rect 1.905x1.905 smd: S5(-1.2,-2.675) S6(1.2,-2.675)
CON_USB_5F_0P65_SM_RA
  rect 0.406x1.422 smd: 1(-1.3,2.525) 2(-0.65,2.525) 3(0,2.525) 4(0.65,2.525) 5(1.3,2.525)
  rect 2.311x1.905 smd: S1(-3.75,-0.325) S2(3.75,-0.325)
DCU8P5R
  oval 1.016x0.305 smd: 1(-1.5,0.75) 2(-1.5,0.25) 3(-1.5,-0.25) 4(-1.5,-0.75) 5(1.5,-0.75) 6(1.5,-0.25) 7(1.5,0.25) 8(1.5,0.75)
DFN8_0P65_3X3_EP_A
  rect 0.356x0.66 smd: 1(-0.975,-1.55) 2(-0.325,-1.55) 3(0.325,-1.55) 4(0.975,-1.55) 5(0.975,1.55) 6(0.325,1.55) 7(-0.325,1.55) 8(-0.975,1.55)
  rect 2.413x1.549 smd: 9(0,0)
DFN8_1P27_8X6_EP_A_A1
  rect 0.762x0.406 smd: 1(-3.875,1.905) 2(-3.875,0.635) 3(-3.875,-0.635) 4(-3.875,-1.905) 5(3.875,-1.905) 6(3.875,-0.635) 7(3.875,0.635) 8(3.875,1.905)
  rect 3.378x4.293 smd: 9(0,0)
DFN2510A-10L_0P5_2P5X1
  rect 0.254x0.66 smd: 1(-1,-0.425)
  rect 0.254x0.61 smd: 2(-0.5,-0.45) 3(0,-0.45) 4(0.5,-0.45) 5(1,-0.45) 6(1,0.45) 7(0.5,0.45) 8(0,0.45) 9(-0.5,0.45) 10(-1,0.45)
DIO-0201
  rect 0.305x0.305 smd: 1(-0.215,0) 2(0.215,0)
DIO-SOD123_D_A1
  rect 0.864x0.864 smd: 1(-1.675,0) 2(1.675,0)
DIO-SOD962-2_A1
  rect 0.152x0.254 smd: 1(-0.2,0) 2(0.2,0)
DIO_POWERDI-123
  rect 2.21x1.397 smd: 1(-0.95,0)
  rect 0.914x1.397 smd: 2(1.6,0)
DIO_SMA
  rect 2.515x1.702 smd: 1(-2,0) 2(2,0)
FPC2X15_4P4_A
  rect 0.203x0.914 smd: 1(-2.8,-1.637) 2(-2.4,-1.637) 3(-2,-1.637) 4(-1.6,-1.637) 5(-1.2,-1.637) 6(-0.8,-1.637) 7(-0.4,-1.637) 8(0,-1.637) 9(0.4,-1.637) 10(0.8,-1.637) 11(1.2,-1.637) 12(1.6,-1.637) 13(2,-1.637) 14(2.4,-1.637) 15(2.8,-1.637) 16(2.8,1.637) 17(2.4,1.637) 18(2,1.637) 19(1.6,1.637) 20(1.2,1.637) 21(0.8,1.637) 22(0.4,1.637) 23(0,1.637) 24(-0.4,1.637) 25(-0.8,1.637) 26(-1.2,1.637) 27(-1.6,1.637) 28(-2,1.637) 29(-2.4,1.637) 30(-2.8,1.637)
  rect 0.711x1.194 smd: S1(-3.7,-1.498) S2(3.7,-1.498) S3(3.7,1.498) S4(-3.7,1.498)
FUSE_0603_0P64
  rect 0.737x0.965 smd: 1(-0.77,0) 2(0.77,0)
GFD40_120
  round 1.016 smd: 1(0,0)
IND2_2P2_4X4
  rect 1.676x2.616 smd: 1(-1.575,0) 2(1.575,0)
IND_0402-POL
  rect 0.533x0.533 smd: 1(-0.4,0) 2(0.4,0)
IND_0806_B_A1
  rect 0.559x1.6 smd: 1(-0.725,0) 2(0.725,0)
LED2_0P9_1X0P6
  rect 0.508x0.61 smd: 1(-0.45,0) 2(0.45,0)
LED2_1P5_1P6X0P8_A_A1
  rect 0.813x0.813 smd: 1(-0.75,0) 2(0.75,0)
LED4_0P7_1P6X0P8
  rect 0.711x0.406 smd: 1(-0.65,0.35) 2(-0.65,-0.35) 3(0.65,0.35) 4(0.65,-0.35)
LED-0603
  rect 1.016x0.914 smd: 1(-0.85,0) 2(0.85,0)
LFD40_80
  round 1.016 smd: 1(0,0)
MECH-M2_RAD4_A1
  round 4.293 smd: 1(0,0)
MH236D126T_A1
  round 5.994 hole 3.2: 1(0,0)
MIC2_1P2_4P1X4P1_TH
  oval 0.889x1.27 hole 0.508: 1(0,0) 2(1.2,0)
MOD-WIFI-BT64_0P7_13P4X13P3
  rect 1.245x1.245 smd: 1(-6.275,-6.225) 17(6.275,-6.225) 33(6.275,6.225) 49(-6.275,6.225)
  rect 0.406x1.245 smd: 2(-4.9,-6.225) 3(-4.2,-6.225) 4(-3.5,-6.225) 5(-2.8,-6.225) 6(-2.1,-6.225) 7(-1.4,-6.225) 8(-0.7,-6.225) 9(0,-6.225) 10(0.7,-6.225) 11(1.4,-6.225) 12(2.1,-6.225) 13(2.8,-6.225) 14(3.5,-6.225) 15(4.2,-6.225) 16(4.9,-6.225) 34(4.9,6.225) 35(4.2,6.225) 36(3.5,6.225) 37(2.8,6.225) 38(2.1,6.225) 39(1.4,6.225) 40(0.7,6.225) 41(0,6.225) 42(-0.7,6.225) 43(-1.4,6.225) 44(-2.1,6.225) 45(-2.8,6.225) 46(-3.5,6.225) 47(-4.2,6.225) 48(-4.9,6.225)
  rect 1.245x0.406 smd: 18(6.275,-4.9) 19(6.275,-4.2) 20(6.275,-3.5) 21(6.275,-2.8) 22(6.275,-2.1) 23(6.275,-1.4) 24(6.275,-0.7) 25(6.275,0) 26(6.275,0.7) 27(6.275,1.4) 28(6.275,2.1) 29(6.275,2.8) 30(6.275,3.5) 31(6.275,4.2) 32(6.275,4.9) 50(-6.275,4.9) 51(-6.275,4.2) 52(-6.275,3.5) 53(-6.275,2.8) 54(-6.275,2.1) 55(-6.275,1.4) 56(-6.275,0.7) 57(-6.275,0) 58(-6.275,-0.7) 59(-6.275,-1.4) 60(-6.275,-2.1) 61(-6.275,-2.8) 62(-6.275,-3.5) 63(-6.275,-4.2) 64(-6.275,-4.9)
  rect 1.016x1.016 smd: G1(-3.85,-3.85) G2(-2.45,-3.85) G3(-1.05,-3.85) G4(1.05,-3.85) G5(2.45,-3.85) G6(3.85,-3.85) G7(-3.85,-2.45) G8(-2.45,-2.45) G9(-1.05,-2.45) G10(1.05,-2.45) G11(2.45,-2.45) G12(3.85,-2.45) G13(-3.85,-1.05) G14(-2.45,-1.05) G15(-1.05,-1.05) G16(1.05,-1.05) G17(2.45,-1.05) G18(3.85,-1.05) G19(-3.85,1.05) G20(-2.45,1.05) G21(-1.05,1.05) G22(1.05,1.05) G23(2.45,1.05) G24(3.85,1.05) G25(-3.85,2.45) G26(-2.45,2.45) G27(-1.05,2.45) G28(1.05,2.45) G29(2.45,2.45) G30(3.85,2.45) G31(-3.85,3.85) G32(-2.45,3.85) G33(-1.05,3.85) G34(1.05,3.85) G35(2.45,3.85) G36(3.85,3.85)
MOSFET_0402-3L_A1
  rect 0.152x0.254 smd: 1(-0.175,-0.325) 2(0.175,-0.325)
  rect 0.508x0.254 smd: 3(0,0.325)
OSC4_1P9_3P2X2P5_C_A1
  rect 1.397x1.194 smd: 1(-1.1,-0.95) 2(1.1,-0.95) 3(1.1,0.95) 4(-1.1,0.95)
OSC4_3P2X2P5_SMD
  rect 1.397x1.194 smd: 1(-1.2,-0.85) 2(1.2,-0.85) 3(1.2,0.85) 4(-1.2,0.85)
QFN16_0P65_4X4_EP_I_A1
  rect 0.991x0.356 smd: 1(-1.9,0.975) 2(-1.9,0.325) 3(-1.9,-0.325) 4(-1.9,-0.975) 9(1.9,-0.975) 10(1.9,-0.325) 11(1.9,0.325) 12(1.9,0.975)
  rect 0.356x0.991 smd: 5(-0.975,-1.9) 6(-0.325,-1.9) 7(0.325,-1.9) 8(0.975,-1.9) 13(0.975,1.9) 14(0.325,1.9) 15(-0.325,1.9) 16(-0.975,1.9)
  rect 2.108x2.108 smd: 17(0,0)
QFN24_0P5_4X4_EP_R_A1
  rect 0.711x0.279 smd: 1(-1.9,1.25) 2(-1.9,0.75) 3(-1.9,0.25) 4(-1.9,-0.25) 5(-1.9,-0.75) 6(-1.9,-1.25) 13(1.9,-1.25) 14(1.9,-0.75) 15(1.9,-0.25) 16(1.9,0.25) 17(1.9,0.75) 18(1.9,1.25)
  rect 0.279x0.711 smd: 7(-1.25,-1.9) 8(-0.75,-1.9) 9(-0.25,-1.9) 10(0.25,-1.9) 11(0.75,-1.9) 12(1.25,-1.9) 19(1.25,1.9) 20(0.75,1.9) 21(0.25,1.9) 22(-0.25,1.9) 23(-0.75,1.9) 24(-1.25,1.9)
  rect 2.261x2.261 smd: 25(0,0)
QFN32_1P5H
  oval 0.254x0.838 smd: 1(-1.751,-2.515) 2(-1.251,-2.515) 3(-0.751,-2.515) 4(-0.25,-2.515) 5(0.25,-2.515) 6(0.751,-2.515) 7(1.251,-2.515) 8(1.751,-2.515) 17(1.751,2.515) 18(1.251,2.515) 19(0.751,2.515) 20(0.25,2.515) 21(-0.25,2.515) 22(-0.751,2.515) 23(-1.251,2.515) 24(-1.751,2.515)
  oval 0.838x0.254 smd: 9(2.515,-1.751) 10(2.515,-1.251) 11(2.515,-0.751) 12(2.515,-0.25) 13(2.515,0.25) 14(2.515,0.751) 15(2.515,1.251) 16(2.515,1.751) 25(-2.515,1.751) 26(-2.515,1.251) 27(-2.515,0.751) 28(-2.515,0.25) 29(-2.515,-0.25) 30(-2.515,-0.751) 31(-2.515,-1.251) 32(-2.515,-1.751)
  rect 3.404x3.404 smd: 33(0,0)
QFN48_0P5_7X7_EP_O_A1
  rect 0.635x0.254 smd: 1(-3.425,2.75) 2(-3.425,2.25) 3(-3.425,1.75) 4(-3.425,1.25) 5(-3.425,0.75) 6(-3.425,0.25) 7(-3.425,-0.25) 8(-3.425,-0.75) 9(-3.425,-1.25) 10(-3.425,-1.75) 11(-3.425,-2.25) 12(-3.425,-2.75) 25(3.425,-2.75) 26(3.425,-2.25) 27(3.425,-1.75) 28(3.425,-1.25) 29(3.425,-0.75) 30(3.425,-0.25) 31(3.425,0.25) 32(3.425,0.75) 33(3.425,1.25) 34(3.425,1.75) 35(3.425,2.25) 36(3.425,2.75)
  rect 0.254x0.635 smd: 13(-2.75,-3.425) 14(-2.25,-3.425) 15(-1.75,-3.425) 16(-1.25,-3.425) 17(-0.75,-3.425) 18(-0.25,-3.425) 19(0.25,-3.425) 20(0.75,-3.425) 21(1.25,-3.425) 22(1.75,-3.425) 23(2.25,-3.425) 24(2.75,-3.425) 37(2.75,3.425) 38(2.25,3.425) 39(1.75,3.425) 40(1.25,3.425) 41(0.75,3.425) 42(0.25,3.425) 43(-0.25,3.425) 44(-0.75,3.425) 45(-1.25,3.425) 46(-1.75,3.425) 47(-2.25,3.425) 48(-2.75,3.425)
  rect 4.089x4.089 smd: 49(0,0)
QFP48P5J
  oval 1.27x0.305 smd: 1(-4.5,2.75) 2(-4.5,2.25) 3(-4.5,1.75) 4(-4.5,1.25) 5(-4.5,0.75) 6(-4.5,0.25) 7(-4.5,-0.25) 8(-4.5,-0.75) 9(-4.5,-1.25) 10(-4.5,-1.75) 11(-4.5,-2.25) 12(-4.5,-2.75) 25(4.5,-2.75) 26(4.5,-2.25) 27(4.5,-1.75) 28(4.5,-1.25) 29(4.5,-0.75) 30(4.5,-0.25) 31(4.5,0.25) 32(4.5,0.75) 33(4.5,1.25) 34(4.5,1.75) 35(4.5,2.25) 36(4.5,2.75)
  oval 0.305x1.27 smd: 13(-2.75,-4.5) 14(-2.25,-4.5) 15(-1.75,-4.5) 16(-1.25,-4.5) 17(-0.75,-4.5) 18(-0.25,-4.5) 19(0.25,-4.5) 20(0.75,-4.5) 21(1.25,-4.5) 22(1.75,-4.5) 23(2.25,-4.5) 24(2.75,-4.5) 37(2.75,4.5) 38(2.25,4.5) 39(1.75,4.5) 40(1.25,4.5) 41(0.75,4.5) 42(0.25,4.5) 43(-0.25,4.5) 44(-0.75,4.5) 45(-1.25,4.5) 46(-1.75,4.5) 47(-2.25,4.5) 48(-2.75,4.5)
R0402
  rect 0.508x0.559 smd: 1(-0.483,0) 2(0.483,0)
R0805
  rect 1.016x1.27 smd: 1(-0.889,0) 2(0.889,0)
SO8_1P27_4X5
  rect 1.6x0.61 smd: 1(-2.7,1.905) 2(-2.7,0.635) 3(-2.7,-0.635) 4(-2.7,-1.905) 5(2.7,-1.905) 6(2.7,-0.635) 7(2.7,0.635) 8(2.7,1.905)
SOIC8_1P27_4X5
  rect 1.524x0.762 smd: 1(-2.725,1.905) 2(-2.725,0.635) 3(-2.725,-0.635) 4(-2.725,-1.905) 5(2.725,-1.905) 6(2.725,-0.635) 7(2.725,0.635) 8(2.725,1.905)
SON6_0P65_2X2_EP_A_A1
  oval 0.508x0.254 smd: 1(-0.95,0.65) 2(-0.95,0) 3(-0.95,-0.65) 4(0.95,-0.65) 5(0.95,0) 6(0.95,0.65)
  rect 0.66x1.346 smd: 7(0,0)
SON8_0P5_2X2_EP
  rect 0.279x0.508 smd: 1(-0.75,-0.95) 2(-0.25,-0.95) 3(0.25,-0.95) 4(0.75,-0.95) 5(0.75,0.95) 6(0.25,0.95) 7(-0.25,0.95) 8(-0.75,0.95)
  rect 1.6x0.914 smd: 9(0,0)
SON10_0P5_3P1X3P1
  rect 0.279x0.864 smd: 1(-1,-1.475) 2(-0.5,-1.475) 3(0,-1.475) 4(0.5,-1.475) 5(1,-1.475) 6(1,1.475) 7(0.5,1.475) 8(0,1.475) 9(-0.5,1.475) 10(-1,1.475)
  custom 0.412x0.412 smd: 11(0,0)
SOT23-3L_1P9_3P12X1P5
  rect 1.016x1.397 smd: 1(-0.95,-1.1) 2(0.95,-1.1) 3(0,1.1)
SOT23-5L_0P95_3P05X1P75
  rect 0.61x1.067 smd: 1(-0.95,-1.35) 2(0,-1.35) 3(0.95,-1.35) 4(0.95,1.35) 5(-0.95,1.35)
SOT23-6L_0P95_3P05X1P75
  rect 0.61x1.067 smd: 1(-0.95,-1.35) 2(0,-1.35) 3(0.95,-1.35) 4(0.95,1.35) 5(0,1.35) 6(-0.95,1.35)
SOT23_123
  rect 0.635x1.016 smd: 1(-0.94,-1.079) 2(0.94,-1.079) 3(0,1.079)
SOT363_6
  rect 0.305x0.762 smd: 1(-0.65,-0.9) 2(0,-0.9) 3(0.65,-0.9) 4(0.65,0.9) 5(0,0.9) 6(-0.65,0.9)
SOT723-3L_0P4_1P2X0P8
  rect 0.279x0.508 smd: 1(-0.4,-0.49) 2(0.4,-0.49)
  rect 0.356x0.508 smd: 3(0,0.49)
SSOP8CR
  oval 0.711x0.254 smd: 1(-1.544,0.75) 2(-1.544,0.25) 3(-1.544,-0.25) 4(-1.544,-0.75) 5(1.544,-0.75) 6(1.544,-0.25) 7(1.544,0.25) 8(1.544,0.75)
SW2_8P25_7P49X4P52
  rect 2.159x1.499 smd: 1(-4.125,0) 2(4.125,0)
SW3_2_8P6X4P3_TH_ST
  rect 1.651x1.651 hole 0.889: 1(0,0)
  round 1.651 hole 0.889: 2(2,0) 3(4,0)
  oval 1.956x2.718 hole 1.575: S1(-2.1,0) S2(6.1,0)
SW4_2P54_6P95X6P55
  rect 2.438x1.143 smd: 1(-4.3,1.27) 2(-4.3,-1.27) 3(4.3,-1.27) 4(4.3,1.27)
SW4_4_6P9X6P2
  rect 2.997x1.016 smd: 1(-4.5,-2) 2(4.5,-2) 3(-4.5,2) 4(4.5,2)
SW16_2P54_21P79X6P7_A1
  rect 1.143x2.438 smd: 1(-8.89,-4.3) 2(-6.35,-4.3) 3(-3.81,-4.3) 4(-1.27,-4.3) 5(1.27,-4.3) 6(3.81,-4.3) 7(6.35,-4.3) 8(8.89,-4.3) 9(8.89,4.3) 10(6.35,4.3) 11(3.81,4.3) 12(1.27,4.3) 13(-1.27,4.3) 14(-3.81,4.3) 15(-6.35,4.3) 16(-8.89,4.3)
TCAP_CASEB
  rect 1.499x2.515 smd: 1(-1.45,0) 2(1.45,0)
TCAP_CASEC
  rect 2.362x2.235 smd: 1(-2.47,0) 2(2.47,0)
TP15
  round 0.381 smd: 1(0,0)
TP30
  round 0.762 smd: 1(0,0)
TP40_SMD
  round 1.016 smd: 1(0,0)
TSSOP16FA
  oval 1.397x0.381 smd: 1(-3,2.275) 2(-3,1.625) 3(-3,0.975) 4(-3,0.325) 5(-3,-0.325) 6(-3,-0.975) 7(-3,-1.625) 8(-3,-2.275) 9(3,-2.275) 10(3,-1.625) 11(3,-0.975) 12(3,-0.325) 13(3,0.325) 14(3,0.975) 15(3,1.625) 16(3,2.275)
UDFN-6L_0P65_2X2_EP
  rect 0.406x0.432 smd: 1(-0.65,-0.938) 2(0,-0.938) 3(0.65,-0.938) 4(0.65,0.938) 5(0,0.938) 6(-0.65,0.938)
  rect 0.965x1.143 smd: 7(-0.325,0)
  rect 0.305x0.762 smd: 8(0.65,0)
VCSP50L1-6_0P5_1P5X1_A1
  round 0.203 smd: A1(-0.5,0.25) A2(0,0.25) A3(0.5,0.25) B1(-0.5,-0.25) B2(0,-0.25) B3(0.5,-0.25)
VQFN48_0P4_6X6_EP_A1
  rect 0.864x0.203 smd: 1(-2.975,2.2) 2(-2.975,1.8) 3(-2.975,1.4) 4(-2.975,1) 5(-2.975,0.6) 6(-2.975,0.2) 7(-2.975,-0.2) 8(-2.975,-0.6) 9(-2.975,-1) 10(-2.975,-1.4) 11(-2.975,-1.8) 12(-2.975,-2.2) 25(2.975,-2.2) 26(2.975,-1.8) 27(2.975,-1.4) 28(2.975,-1) 29(2.975,-0.6) 30(2.975,-0.2) 31(2.975,0.2) 32(2.975,0.6) 33(2.975,1) 34(2.975,1.4) 35(2.975,1.8) 36(2.975,2.2)
  rect 0.203x0.864 smd: 13(-2.2,-2.975) 14(-1.8,-2.975) 15(-1.4,-2.975) 16(-1,-2.975) 17(-0.6,-2.975) 18(-0.2,-2.975) 19(0.2,-2.975) 20(0.6,-2.975) 21(1,-2.975) 22(1.4,-2.975) 23(1.8,-2.975) 24(2.2,-2.975) 37(2.2,2.975) 38(1.8,2.975) 39(1.4,2.975) 40(1,2.975) 41(0.6,2.975) 42(0.2,2.975) 43(-0.2,2.975) 44(-0.6,2.975) 45(-1,2.975) 46(-1.4,2.975) 47(-1.8,2.975) 48(-2.2,2.975)
  rect 4.394x4.394 smd: 49(0,0)
X2SON4_0P65_1X1_EP_A_A1
  custom 0.077x0.077 smd: 1(-0.43,0.325) 2(-0.43,-0.325) 3(0.43,-0.325) 4(0.43,0.325)
  rect 0.559x0.559 smd rot 45: 5(0,0)
XTAL2_2P5_3P2X1P5
  rect 1.016x1.803 smd: 1(-1.25,0) 2(1.25,0)
XTAL2_3P8_5X3P2
  rect 1.803x2.413 smd: 1(-1.9,0) 2(1.9,0)
XTAL4_1P7_3P2X2P5
  rect 1.422x1.219 smd: 1(-1.1,-0.85) 2(1.1,-0.85) 3(1.1,0.85) 4(-1.1,0.85)
XTAL4_1P85_3P2X2P5
  rect 1.321x1.067 smd: 1(-1.15,-0.925) 2(1.15,-0.925) 3(1.15,0.925) 4(-1.15,0.925)
XTAL4_2P54_7X5_A_A1
  rect 2.21x1.397 smd: 1(-3.15,-1.27) 2(-3.15,1.27) 3(3.15,1.27) 4(3.15,-1.27)

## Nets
3V3OUT: C240.1 U18.6
5VIN: C394.1 C395.1 F1.2 Q2.4 Q2.8(SOURCE2) Q17.2(EMITTER) R4.1 R538.2 R539.2
AVCC_DBG_5V0: R157.2 U18.46
GND: BH1.2 C1.2(CATHODE) C2.2 C3.2 C40.2 C41.2 C42.2 C44.2 C45.2 C46.2 C47.2 C48.2 C49.2 C50.2 C51.2 C52.2 C53.2 C63.2 C64.2 C65.2 C66.2 C67.2 C68.2 C69.2 C70.2 C71.2 C72.2 C73.2 C74.2 C75.2 C76.2 C77.2 C78.2 C79.2 C80.2 C81.2 C82.2 C83.2 C84.2 C85.2 C86.2 C87.2 C88.2 C89.2 C90.2 C91.2 C92.2 C93.2 C94.2 C95.2 C96.2 C97.2 C98.2 C99.2 C100.2 C101.2 C102.2 C103.2 C104.2 C105.2 C106.2 C107.2 C108.2 C109.2 C110.2 C111.2 C112.2 C113.2 C114.2 C115.2 C116.2 C117.2 C118.2 C119.2 C120.2 C121.2 C122.2 C123.2 C124.2 C125.2 C126.2 C127.2 C128.2 C129.2 C130.2 C131.2 C140.2 C141.2 C142.2 C143.2 C144.2 C145.2 C146.2 C147.2 C148.2 C149.2 C150.2 C151.2 C152.2 C153.2 C154.2 C155.2 C156.2 C157.2 C158.2 C159.2 C160.2 C161.2 C162.2 C163.2 C164.2 C165.2 C166.2 C167.2 C168.2 C169.2 C170.2 C171.2 C172.2 C173.2 C174.2 C175.2 C176.2 C177.2 C178.2 C179.2 C180.2 C181.2 C182.2 C183.2 C184.2 C185.2 C186.2 C187.2 C188.2 C189.2 C190.2 C195.2 C196.2 C197.2 C199.2(CATHODE) C200.2 C201.2 C202.2(CATHODE) C203.2(CATHODE) C204.2(CATHODE) C216.2 C217.2 C218.2 C219.2 C220.2 C221.2 C222.2 C223.2 C224.2 C226.2 C227.2 C228.2 C239.2 C240.2 C241.2 C242.2 C243.1 C244.1 C245.2 C249.2 C250.2 C251.2 C252.2 C261.2 C262.2 C263.2 C264.2 C265.2 C266.1 C267.2 C268.2 C269.2 C270.2 C271.2 C272.2 C273.2 C279.2 C280.2 C281.2 C282.2 C283.2 C284.2 C285.2 C286.2 C287.2 C288.2 C289.2 C290.2 C291.2 C292.2 C293.2 C294.2 C295.2 C296.2 C297.2 C298.2 C299.2(CATHODE) C300.1 C301.2 C302.2 C303.2 C304.2 C305.2 C306.2 C307.2 C308.2 C309.2 C310.2 C311.2 C354.2 C357.2 C361.2 C362.2 C366.2 C367.2 C368.2 C369.2 C370.2 C391.2 C392.2 C393.2 C395.2 C401.2 C402.2 C403.2 C404.2 C405.2 C406.2 C407.2 C408.2 C409.2 C410.2 C420.1 C421.1 C422.1 C423.1 C438.2(CATHODE) C439.2 C444.2 C445.2 C446.2 C447.2 C448.2 C456.2 C460.2 C461.2 C500.2 C501.2 C503.2 C504.2 C505.2 C506.2 C507.2 C508.2 C509.2 C510.2 C511.2 C512.2 C513.2 C518.2 C519.2 C520.2 C523.2 C524.2 C525.2 C527.2 C528.2 C533.2 C534.2 C535.2 C536.2 C537.2 C538.2 C539.2 C540.2 C542.2 C543.2 C544.2 C546.2 C550.2 C551.2 C552.2 C553.2 C556.1 C557.2 C558.2 C559.2 C560.2 C561.2 C566.2 C567.2 C568.2 C569.2 C570.2 C571.2 C572.2 C573.2 C576.2 C577.2 C578.2 C579.2 D1.1(K) D17.2 D23.1 D24.1 D27.1 D28.1 D29.1 D30.1 D35.1(K) H1.6 H2.3 H2.5 H5.6 J1.2 J1.S1 J1.S2 J2.2 J3.2 J3.3 J4.2 J4.3 J7.C5 J8.4 J8.9 J8.15 J8.18 J8.21 J8.26 J8.27 J8.29 J8.34 J8.35 J8.37 J8.40 J8.43 J8.50 J8.S1 J8.S2 J10.2 J10.3 J11.5 J14.9 J14.18 J14.27 J14.31 J14.33 J14.44 J15.1 J19.5 J19.6 J19.SH1 J19.SH2 J20.6 J20.11 J20.12 J20.14 J20.15 J20.18 J20.21 J20.24 J20.26 J20.29 J20.S1 J20.S2 J20.S3 J20.S4 J25.5 J26.4 J27.10 J27.SH1 J27.SH2 J28.3 J28.6 J28.S1 J28.S2 J28.S3 J28.S4 L8.2 M1.1 M1.7 M1.9 M1.15 M1.16 M1.17 M1.19 M1.20 M1.23(GND9) M1.24 M1.28 M1.29 M1.30 M1.31 M1.33 M1.34 M1.35 M1.37 M1.39 M1.44 M1.45 M1.48 M1.49 M1.54 M1.55 M1.59 M1.61 M1.63 M1.64 M1.G1 M1.G2 M1.G3 M1.G4 M1.G5 M1.G6 M1.G7 M1.G8 M1.G9 M1.G10 M1.G11 M1.G12 M1.G13 M1.G14 M1.G15 M1.G16 M1.G17 M1.G18 M1.G19 M1.G20 M1.G21 M1.G22 M1.G23 M1.G24 M1.G25 M1.G26 M1.G27 M1.G28 M1.G29 M1.G30 M1.G31 M1.G32 M1.G33 M1.G34 M1.G35 M1.G36 MH1.1 MH2.1 MH3.1 MH4.1 P4.1 P5.1 P6.1 P7.1 P8.1 P10.1 P11.1 P12.1 P13.1 P14.1 P17.1 P18.1 P19.1 P20.1 P21.1 P22.1 P23.1 P24.1 P25.1 P26.1 P27.1 Q5.2(SOURCE) Q7.2(SOURCE) Q8.2(EMITTER) Q25.2(SOURCE) Q37.2(SOURCE) Q40.2(EMITTER) R8.1 R35.2 R37.1 R40.1 R66.1 R67.1 R68.2 R70.1 R71.1 R75.1 R76.1 R80.1 R81.2 R82.1 R83.1 R84.1 R86.1 R116.2 R117.2 R118.2 R126.1 R131.1 R155.2 R163.2 R174.1 R250.2 R251.2 R254.1 R269.2 R293.2 R294.1 R297.2 R300.1 R303.2 R307.1 R308.1 R349.2 R367.1 R449.2 R567.2 R568.2 R604.2 R606.2 R608.2 R614.1 R615.2 R616.1 R634.1 R635.1 R641.2 R660.1 R666.1 R667.1 R668.1 R669.2 R678.1 R679.2 R683.2 R691.1 R696.1 R697.1 R698.1 R699.1 R700.1 R701.1 R702.1 R703.1 R704.1 R717.1 R735.1 R741.2 R742.1 R764.1 SW1.2 SW4.1 SW4.2 SW5.1 SW5.2 SW6.1 SW6.2 SW7.1 SW7.2 SW8.1 SW8.2 SW9.1 TP14.1 TP30.1 TP31.1 TP32.1 TP33.1 TP34.1 TP35.1 TP36.1 TP37.1 TP68.1 TP69.1 TP70.1 TP71.1 TP72.1 TP73.1 TP74.1 TP75.1 U5.20 U5.21 U5.22 U5.23 U5.24 U5.25 U5.27 U5.49 U7.A1 U7.A3 U7.A6 U7.A9 U7.A13 U7.A17 U7.A21 U7.A25 U7.AA1 U7.AA2 U7.AA6 U7.AA8 U7.AA15 U7.AA23 U7.AB1 U7.AB2 U7.AB4 U7.AB5 U7.AB7 U7.AB9 U7.AB12 U7.AC1 U7.AC2 U7.AC6 U7.AC9 U7.AC12 U7.AC15 U7.AC17 U7.AC19 U7.AC21 U7.AC23 U7.AD1 U7.AD2 U7.AD3 U7.AD5 U7.AD7 U7.AD9 U7.AD12 U7.AE1 U7.AE2 U7.AE3 U7.AE5 U7.AE7 U7.AE9 U7.AE12 U7.AE24 U7.AE25(VSS_141) U7.B3 U7.B6 U7.B9 U7.B13 U7.B17 U7.B21 U7.C9 U7.C13 U7.C15 U7.C16 U7.C18 U7.C19 U7.D1 U7.D2 U7.D4 U7.D7 U7.D10 U7.D22 U7.F7 U7.F8 U7.F11 U7.F13 U7.G4 U7.G7 U7.G9 U7.G11 U7.G13 U7.G15 U7.G17 U7.G19 U7.G22 U7.H1 U7.H2 U7.J7 U7.J19 U7.K4 U7.K10 U7.K12 U7.K14 U7.K16 U7.K22 U7.L7 U7.L11 U7.L13 U7.L15 U7.L19 U7.M10 U7.M12 U7.M14 U7.M16 U7.M24 U7.M25 U7.N4 U7.N7 U7.N11 U7.N13 U7.N15 U7.N19 U7.P10 U7.P12 U7.P14 U7.P16 U7.R7 U7.R11 U7.R13 U7.R15 U7.R19 U7.R20 U7.R21 U7.R23 U7.T4 U7.T10 U7.T12 U7.T14 U7.T16 U7.T20 U7.U7 U7.U11 U7.U19 U7.U20 U7.U23 U7.V20 U7.W1 U7.W2 U7.W4 U7.W7 U7.W9 U7.W11 U7.W13 U7.W15 U7.W17 U7.W19 U7.W20 U7.W23 U7.Y6 U7.Y13 U7.Y14 U7.Y15 U7.Y16 U7.Y17 U7.Y18 U7.Y19 U8.A9 U8.B1 U8.B3 U8.B9 U8.D1 U8.D8 U8.E1 U8.E2 U8.E8 U8.F9 U8.G1 U8.G8 U8.G9 U8.J2 U8.J8 U8.M1 U8.M9 U8.P1 U8.P9 U8.T1 U8.T9 U9.A9 U9.B1 U9.B3 U9.B9 U9.D1 U9.D8 U9.E1 U9.E2 U9.E8 U9.F9 U9.G1 U9.G8 U9.G9 U9.J2 U9.J8 U9.M1 U9.M9 U9.P1 U9.P9 U9.T1 U9.T9 U10.A6 U10.C4 U10.E7 U10.G5 U10.H10 U10.J5 U10.K8 U10.N2 U10.N5 U10.P4 U10.P6 U11.4 U11.9 U13.49 U17.4 U18.9 U18.18 U18.25 U18.34 U18.45 U18.47 U19.4 U23.6 U24.9 U24.20 U24.24 U24.28 U24.33 U25.2 U25.9(VSS_EP) U30.6 U31.3 U31.7 U33.3 U37.2 U41.1 U41.2 U41.3 U41.4 U41.7(WP) U42.5 U42.6 U42.10 U42.15 U42.21 U42.24 U42.25 U45.2 U46.1 U46.3 U46.9 U47.2 U47.5 U49.2 U49.5 U50.3 U50.5 U50.17 U51.4 U51.8 U51.11 U52.3 U52.17 U53.3 U53.8 U54.3 U54.8 U55.B2 X2.2 X2.4(GND2) X3.2 X3.4(GND2) X5.2 X5.4(GND2) Y4.2 Y5.2
GND_USB_A: C301.1 J26.S1 J26.S2 J26.S3 J26.S4 R250.1
GND_USB_CONN: C242.1 J11.S1 J11.S2 J11.S3 J11.S4 J11.S5 J11.S6 R163.1
PVCC_ENET_CAP: C115.1 U7.H14
PVCC_EPDC_LCD_CAP: C116.1 U7.N17
PVCC_GPIO_CAP: C100.1 U7.V10
PVCC_I2C_SPI_UART_CAP: C128.1 U7.R9
PVCC_SAI_SD_CAP: C111.1 U7.J9
VCCI_EMMC: C510.1 C511.1 U10.C2
VDD_1P2_CAP: C88.1 C89.1 U7.H12 U7.U9
VDD_1V8: C124.1 C129.1 C216.1 C406.1 C407.1 C409.1 C410.1 C461.1 C509.1 C561.1 C574.1 C575.1 FB2.1 FB3.1 FB4.1 FB19.2 FB35.1 FB36.2 FB39.2 M1.38 Q39.1 R30.2 R32.1 R45.1 R325.1 R605.1 R607.1 R636.2 R638.1 R639.1 R640.2 R682.2 R707.2 R708.2 R709.2 R710.2 R711.2 R722.2 TP77.1 U5.39 U7.L9 U42.3 U42.7 U42.11 U42.20 U45.3 U50.1 U55.A2
VDD_1V8_L3: L5.1 U5.38
VDD_1V8_SNS: C42.1 C546.1 C552.1 L5.2 R722.1 U5.5 U50.2
VDD_1V35: C142.1 C143.1 C144.1 C145.1 C146.1 C147.1 C148.1 C149.1 C150.1 C151.1 C152.1 C153.1 C154.1 C155.1 C156.1 C157.1 C158.1 C159.1 C160.1 C161.1 C162.1 C163.1 C164.1 C165.1 C166.1 C167.1 C168.1 C169.1 C170.1 C171.1 C172.1 C173.1 C174.1 C175.1 C176.1 C177.1 C178.1 C179.1 C180.1 C533.1 C537.1 R85.2 R716.2 R721.2 TP19.1 TP20.1 TP78.1 U5.41 U7.AA16 U7.AA17 U7.AA18 U7.AA19 U7.AA20 U7.AA21 U7.T21 U7.U21 U7.V21 U7.W21 U7.Y21 U8.A1 U8.A8 U8.B2 U8.C1 U8.C9 U8.D2 U8.D9 U8.E9 U8.F1 U8.G7 U8.H2 U8.H9 U8.K2 U8.K8 U8.N1 U8.N9 U8.R1 U8.R9 U9.A1 U9.A8 U9.B2 U9.C1 U9.C9 U9.D2 U9.D9 U9.E9 U9.F1 U9.G7 U9.H2 U9.H9 U9.K2 U9.K8 U9.N1 U9.N9 U9.R1 U9.R9 U50.14 U51.2
VDD_1V35_L2: L4.1 U5.42
VDD_1V35_SNS: C41.1 C551.1 L4.2 R721.1 U50.15
VDD_3V3: C98.1 C99.1 C101.1 C109.1 C112.1 C113.1 C114.1 C117.1 C118.1 C122.1 C127.1 C181.1 C182.1 C183.1 C189.1 C190.1 C194.1 C217.1 C218.1 C241.1 C245.1 C267.1 C268.1 C391.1 C408.1 C460.1 C505.1 C536.1 C543.1 C544.1 C566.1 C567.1 C574.2 C575.2 C577.1 FB21.2 FB38.1 FB41.1 H5.1 M1.46 M1.47 Q6.2(SOURCE) Q25.1 Q38.2(SOURCE) R33.2 R34.2 R46.1 R61.2 R62.2 R63.2 R64.2 R92.1 R102.1 R104.1 R105.1 R168.2 R169.2 R170.2 R171.2 R224.2 R231.2 R235.2 R252.2 R253.2 R255.2 R257.2 R295.2 R296.2 R387.2 R637.2 R658.1 R674.1 R685.1 R686.1 R692.1 R715.1 R727.2 R728.2 R731.2 R732.2 R733.1 R734.1 R739.2 R740.2 R749.2 R750.2 R751.1 SW2.9 SW2.10 SW2.11 SW2.12 SW2.13 SW2.14 SW2.15 SW2.16 TP80.1 U7.F9 U7.F10 U7.F12 U7.H16 U7.K18 U7.L17 U7.M8 U7.M18 U7.N9 U7.P8 U7.T8 U10.E6 U10.F5 U10.J10 U10.K9 U11.8 U17.8(VCC) U19.8(VCC) U24.8 U24.10 U25.5 U31.1(VDD) U41.8 U45.7(VCCB) U50.4 U50.16 U51.10 U52.1 U52.4 U52.16
VDD_3V3_L4A: L6.1 U5.13
VDD_3V3_L4B: L6.2 U5.14
VDD_3V3_LCD: C263.1 C264.1 C265.1 C392.1 C558.1 J14.45 J14.46 Q38.3 R656.1 R733.2 U23.1 U23.7 U23.10 U33.5
VDD_3V3_PERI: C199.1 C200.1 C201.1 C202.1 C203.1 C204.1 C518.1 C520.1 C524.1 C531.1 D5.1 D6.2 D7.2 FB38.2 J8.2 J8.24 J8.39 J8.41 J8.52 L7.2 R694.2 TP84.1 U47.4 U49.4
VDD_3V3_SD: C45.1 C560.1 U5.30 U55.A1
VDD_3V3_SNS: C46.1 C47.1 R728.1 U5.15 U5.31 U52.2
VDD_5V: C261.1 C262.1 C525.1 FB37.2 FB40.1 J14.47 J14.48 R730.2 TP82.1 U30.7 U52.11
VDD_5V_SNS: C48.1 C49.1 R730.1 U5.7 U5.33 U52.12
VDD_CAN: C279.1 C570.1 FB37.1 U25.3
VDD_CLKGEN_1V8: C527.1 C528.1 FB39.1 R705.2 Y5.4(VDD)
VDD_CSI_2V8_1: C444.1 C445.1 FB31.2 J20.3
VDD_CSI_2V8_2: C354.1 C501.1 FB32.2 J20.5
VDD_CSI_XCLK: C448.1 FB35.2 R623.1 Y4.4(VDD)
VDD_DCJACK_5VIN: F1.1 J1.1
VDD_DDR_VTT: C538.1 C539.1 C540.1 U51.3 U51.5(VOSNS)
VDD_HOST_VBUS: C123.1 R69.1 R71.2 U7.C10
VDD_LDO_1V5: C503.1 C504.1 J8.6 J8.28 J8.48 R729.2 TP81.1 U52.14
VDD_LDO_1V5_SNS: C44.1 C553.1 R729.1 U5.4 U52.15
VDD_LDO_2V5: C523.1 FB20.2 TP86.1 U49.1(OUT)
VDD_LDO_2V8: C519.1 FB31.1 FB32.1 TP85.1 U47.1(OUT)
VDD_LPSR_1P0_CAP: C97.1 U7.AC5
VDD_LPSR_IN: C96.1 R32.2 U7.W6
VDD_OTG1_1P0_CAP: C119.1 C120.1 U7.H10
VDD_OTG2_1P0_CAP: C125.1 C126.1 U7.J11
VDD_OTG_VBUS: C121.1 R65.1 R67.2 U7.C8
VDD_PHY_1V0: C251.1 C302.1 C303.1 C306.1 C307.1 C308.1 C309.1 C310.1 C311.1 C500.1 FB22.1 U13.6 U13.24 U13.31 U13.42
VDD_SD: C104.1 C559.1 R99.1 R100.1 R101.1 R491.2 U7.E7 U55.B1(VOUT)
VDD_SD2: C108.1 R325.2 U7.H8
